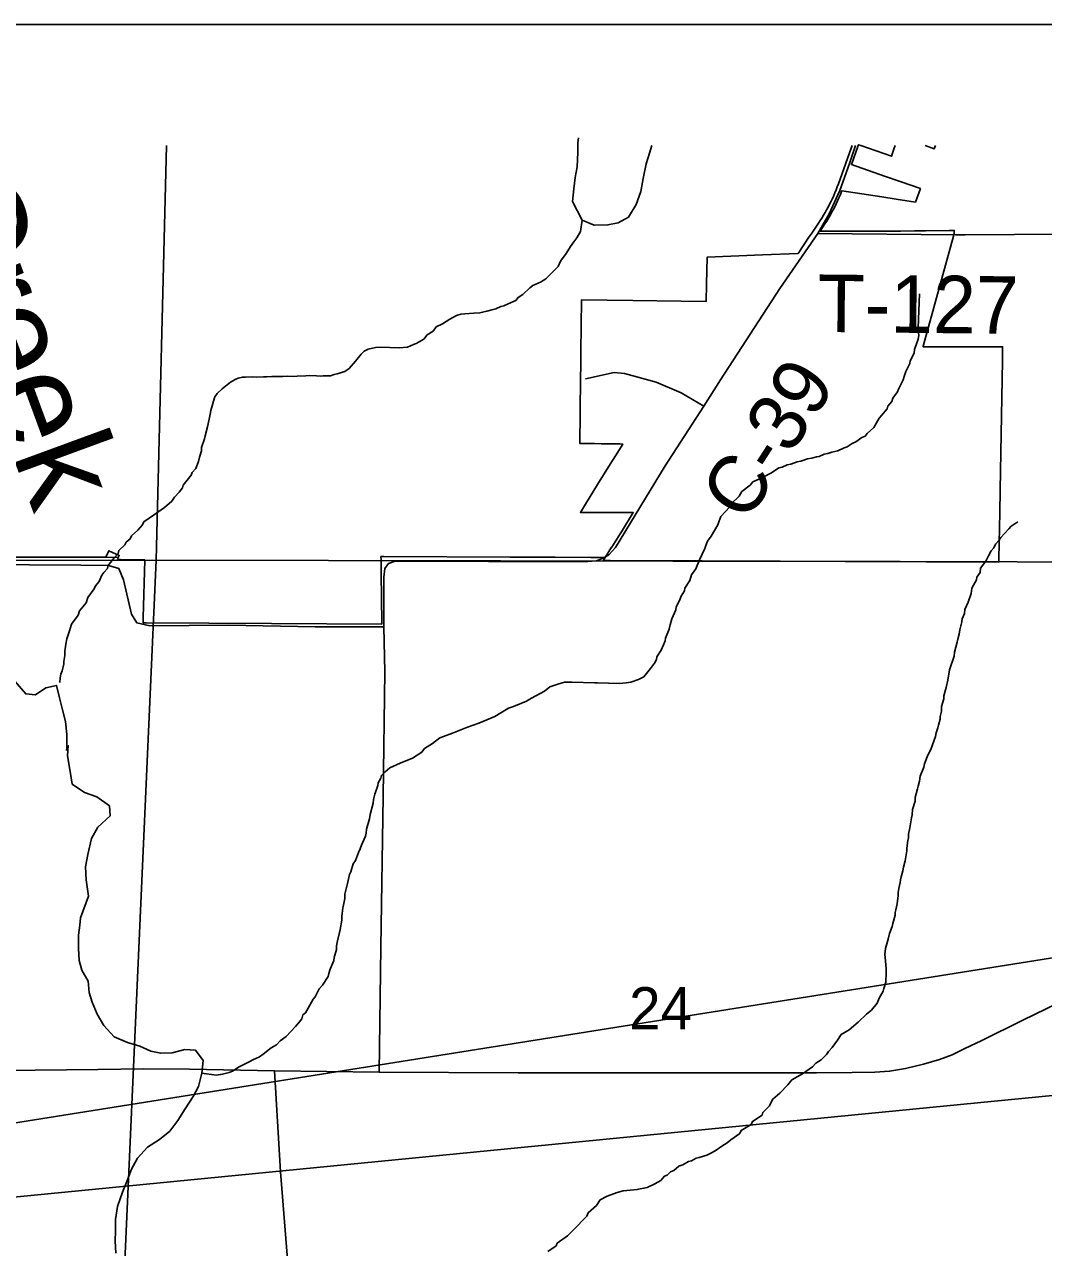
# Model space of a CAD drawing. Extents: x 0 to 34, y 0 to 22.
# Drawn here: x 4.944 to 5.951, y 16.112 to 17.321 of the extents above; entities that cross this region are included whole.
import ezdxf

# ---------------------------------------------------------------- set-up
doc = ezdxf.new("R2010")
doc.units = 0
for name, color, linetype in [('GM_X_County_Road', 7, 'Continuous'), ('GM_X_County_Road_Text', 7, 'Continuous'), ('GM_X_Interchange_Ramps', 7, 'Continuous'), ('GM_X_Minor_Lake', 7, 'Continuous'), ('GM_X_Minor_River', 7, 'Continuous'), ('GM_X_Minor_River_Text', 7, 'Continuous'), ('GM_X_Section', 7, 'Continuous'), ('GM_X_Section_Text', 7, 'Continuous'), ('GM_X_Township_Road', 7, 'Continuous'), ('GM_X_Township_Road_Text', 7, 'Continuous'), ('SH_Data', 7, 'Continuous'), ('SH_Text', 7, 'Continuous')]:
    doc.layers.add(name, color=color, linetype=linetype)

msp = doc.modelspace()

# ---------------------------------------------------------------- linework, layer by layer
at = {"layer": 'GM_X_County_Road'}
msp.add_line((5.1909, 16.287), (5.2943, 16.2857), dxfattribs=at)
for points in [[(5.5248, 16.8009), (5.5278, 16.8041), (5.577, 16.8848), (5.615, 16.944), (5.6316, 16.9698), (5.6902, 17.0601), (5.7276, 17.1146), (5.7389, 17.1338), (5.7495, 17.1571), (5.759, 17.1837), (5.7648, 17.2013)], [(5.2943, 16.2857), (5.2959, 16.4093), (5.2984, 16.5581), (5.2998, 16.6814), (5.2989, 16.7257), (5.2988, 16.7749), (5.2998, 16.7833), (5.3036, 16.7884), (5.3102, 16.7908), (5.3165, 16.7908), (5.4022, 16.7902), (5.5005, 16.7904), (5.5091, 16.7911), (5.5156, 16.7937), (5.5211, 16.7969), (5.5248, 16.8009)], [(5.0905, 15.3548), (5.088, 15.4096), (5.0858, 15.4458), (5.0858, 15.4573), (5.0873, 15.4677), (5.0936, 15.4924), (5.1042, 15.5268), (5.1258, 15.5877), (5.154, 15.6678), (5.187, 15.7631), (5.1955, 15.7965), (5.2044, 15.8401), (5.2156, 15.895), (5.2181, 15.9129), (5.2189, 15.9255), (5.2185, 15.9366), (5.2096, 16.0226), (5.2035, 16.1047), (5.197, 16.1872), (5.1909, 16.287)]]:
    msp.add_lwpolyline(points, dxfattribs=at)
at = {"layer": 'GM_X_Interchange_Ramps'}
for points in [[(5.8042, 17.2013), (5.8032, 17.1987), (5.8005, 17.1909), (5.7701, 17.2014), (5.768, 17.2022), (5.7673, 17.2004), (5.7609, 17.1826), (5.7937, 17.1712), (5.809, 17.1659), (5.8291, 17.1588), (5.8241, 17.1456), (5.805, 17.1485), (5.7911, 17.1506), (5.7515, 17.1567), (5.7498, 17.1525), (5.7486, 17.1496), (5.7472, 17.1467), (5.7459, 17.1438), (5.7444, 17.1407), (5.7429, 17.1379), (5.7414, 17.1351), (5.7398, 17.1323), (5.7382, 17.1296), (5.7365, 17.1268), (5.7348, 17.1241), (5.7331, 17.1215), (5.73, 17.1169), (5.8095, 17.1169), (5.8233, 17.1171), (5.8341, 17.1172), (5.8576, 17.1175), (5.8625, 17.1175), (5.8625, 17.1147), (5.8617, 17.1118), (5.8318, 17.0031), (5.8317, 17.0026), (5.9103, 17.0025), (5.9101, 16.9888), (5.9094, 16.9525), (5.9084, 16.898), (5.9078, 16.8608), (5.9074, 16.8388), (5.9069, 16.8084), (5.9067, 16.7931), (5.9066, 16.7898), (5.8923, 16.7899), (5.878, 16.7899), (5.835, 16.7901), (5.809, 16.7902), (5.7931, 16.7902), (5.7859, 16.7902), (5.6905, 16.7906), (5.6277, 16.7908), (5.6134, 16.7909), (5.6054, 16.7909), (5.5827, 16.791), (5.5224, 16.7912), (5.5175, 16.7912), (5.5157, 16.7912), (5.5159, 16.7916), (5.5176, 16.7944), (5.5162, 16.7944), (5.5067, 16.7944), (5.5033, 16.7944), (5.4681, 16.7945), (5.4237, 16.7947), (5.299, 16.7951), (5.2961, 16.7951), (5.2962, 16.7918), (5.2963, 16.7783), (5.2968, 16.7301), (5.2968, 16.7285), (5.1879, 16.7291), (5.0642, 16.7297), (5.0611, 16.7297), (5.0612, 16.7349), (5.0628, 16.7915), (5.0628, 16.7918), (5.0426, 16.7921), (5.0388, 16.7922), (5.0357, 16.7922), (5.0361, 16.793), (5.0366, 16.7942), (5.0243, 16.7946), (5.0223, 16.7947), (5.0209, 16.7947), (5.02, 16.7947), (5.0172, 16.7947), (5.002, 16.7947), (4.9656, 16.7946), (4.9245, 16.7945)], [(4.9245, 16.7945), (4.9656, 16.7946), (5.002, 16.7947), (5.0172, 16.7947), (5.02, 16.7947), (5.0209, 16.7947), (5.0223, 16.7947), (5.0243, 16.7946), (5.0271, 16.801), (5.0375, 16.7964), (5.0366, 16.7942), (5.0361, 16.793), (5.0357, 16.7922), (5.0388, 16.7922), (5.0426, 16.7921), (5.0628, 16.7918), (5.0628, 16.7915), (5.0612, 16.7349), (5.0611, 16.7297), (5.0642, 16.7297), (5.1879, 16.7291), (5.2968, 16.7285), (5.2968, 16.7301), (5.2963, 16.7783), (5.2962, 16.7918), (5.2961, 16.7951), (5.299, 16.7951), (5.4237, 16.7947), (5.4681, 16.7945), (5.5033, 16.7944), (5.5067, 16.7944), (5.5176, 16.7944), (5.5239, 16.8044), (5.5241, 16.8046), (5.5323, 16.8175), (5.5337, 16.8198), (5.5453, 16.8386), (5.5118, 16.8387), (5.4931, 16.8388), (5.4982, 16.8469), (5.5102, 16.8664), (5.5226, 16.8864), (5.5277, 16.8946), (5.535, 16.9064), (5.532, 16.9065), (5.5137, 16.9067), (5.5071, 16.9068), (5.4925, 16.907), (5.4929, 16.9369), (5.4934, 16.9733), (5.4935, 16.9827), (5.4937, 16.9975), (5.4944, 17.049), (5.5196, 17.0487), (5.5449, 17.0484), (5.5926, 17.0477), (5.6175, 17.0474), (5.6179, 17.0644), (5.6185, 17.0911), (5.6731, 17.0933), (5.7082, 17.0948), (5.719, 17.1107), (5.7211, 17.1139), (5.7224, 17.1158), (5.7283, 17.1247), (5.73, 17.1272), (5.7317, 17.1298), (5.7333, 17.1325), (5.7349, 17.1351), (5.7364, 17.1378), (5.7379, 17.1406), (5.7394, 17.1435), (5.7408, 17.1463), (5.7421, 17.1491), (5.7434, 17.1519), (5.7446, 17.1547), (5.7458, 17.1576), (5.7469, 17.1605), (5.7481, 17.1636), (5.759, 17.1941), (5.7616, 17.2013)], [(5.8439, 17.2013), (5.8428, 17.1982), (5.8339, 17.2013)]]:
    msp.add_lwpolyline(points, dxfattribs=at)
at = {"layer": 'GM_X_Minor_Lake'}
for points in [[(5.4912, 17.209), (5.4907, 17.2041), (5.4905, 17.1946), (5.4898, 17.1805), (5.4881, 17.1699), (5.4867, 17.1586), (5.4853, 17.146), (5.4949, 17.1276)], [(5.4949, 17.1276), (5.5069, 17.1228), (5.5203, 17.1229), (5.5306, 17.125), (5.5406, 17.1305), (5.5481, 17.1433), (5.5529, 17.1561), (5.5551, 17.169), (5.558, 17.1834), (5.5613, 17.194), (5.5636, 17.2013)]]:
    msp.add_lwpolyline(points, dxfattribs=at)
at = {"layer": 'GM_X_Minor_River'}
for points in [[(5.3789, 17.0351), (5.3877, 17.0356), (5.3938, 17.0362), (5.3965, 17.0366), (5.4007, 17.0376), (5.4068, 17.0394), (5.4095, 17.0401), (5.4145, 17.0422), (5.4176, 17.0429), (5.4219, 17.0451), (5.4292, 17.0483), (5.4315, 17.0513), (5.4362, 17.0543), (5.4432, 17.0609), (5.4463, 17.0632), (5.4537, 17.0664), (5.4591, 17.0697), (5.4657, 17.0764), (5.4712, 17.082), (5.4736, 17.0873), (5.4792, 17.0947), (5.4835, 17.1015), (5.4867, 17.1064), (5.4895, 17.1101), (5.4931, 17.1165), (5.4949, 17.1276)], [(5.5818, 16.7278), (5.5834, 16.7335), (5.5875, 16.7425), (5.5879, 16.7455), (5.5912, 16.7519), (5.5928, 16.7561), (5.596, 16.7613), (5.5964, 16.764), (5.6012, 16.7715), (5.6029, 16.7772), (5.6072, 16.7832), (5.6109, 16.7918), (5.6161, 16.8031), (5.617, 16.8062), (5.6186, 16.8103), (5.6225, 16.8155), (5.6289, 16.8264), (5.6298, 16.8295), (5.6318, 16.8347), (5.6408, 16.8444), (5.642, 16.8474), (5.6499, 16.8549), (5.6526, 16.8594), (5.6608, 16.8657), (5.6636, 16.869), (5.6717, 16.8726), (5.6821, 16.8781), (5.6891, 16.8829), (5.6925, 16.8836), (5.6975, 16.8857), (5.701, 16.8864), (5.7072, 16.8889), (5.711, 16.8896), (5.7175, 16.8917), (5.7217, 16.8924), (5.7263, 16.8938), (5.729, 16.8941), (5.734, 16.8963), (5.7375, 16.8969), (5.7417, 16.8984), (5.7475, 16.8997), (5.7536, 16.9026), (5.7567, 16.9037), (5.7618, 16.907), (5.7652, 16.9085), (5.7711, 16.9129), (5.7745, 16.9143), (5.7765, 16.9169), (5.7831, 16.9229), (5.7883, 16.9319), (5.7907, 16.9345), (5.7962, 16.9412), (5.797, 16.9439), (5.8009, 16.9483), (5.8018, 16.9517), (5.8065, 16.9581), (5.8074, 16.9608), (5.8122, 16.9698), (5.813, 16.9732), (5.8147, 16.9781), (5.8187, 16.986), (5.8191, 16.9886), (5.8228, 16.9962), (5.8232, 17), (5.8269, 17.0102), (5.8274, 17.0136), (5.8271, 17.0163), (5.8268, 17.0212), (5.8281, 17.0547)], [(4.9788, 16.6707), (4.9793, 16.6753), (4.9797, 16.6791), (4.981, 16.6821), (4.9827, 16.6889), (4.9827, 16.6916), (4.9836, 16.6973), (4.9838, 16.7018), (4.9847, 16.7087), (4.9856, 16.714), (4.9885, 16.7219), (4.9905, 16.7283), (4.9969, 16.7373), (4.9981, 16.7415), (5.0048, 16.7493), (5.0065, 16.7546), (5.0128, 16.7632), (5.014, 16.7662), (5.0176, 16.7707), (5.0204, 16.7768), (5.0224, 16.7794), (5.0259, 16.7835), (5.0267, 16.7865), (5.0326, 16.794), (5.0366, 16.7981), (5.037, 16.8011), (5.0429, 16.8067), (5.0445, 16.8093), (5.0484, 16.8127), (5.0496, 16.8157), (5.0558, 16.8212), (5.0605, 16.8265), (5.0618, 16.8295), (5.0722, 16.8368), (5.0823, 16.8438), (5.0894, 16.8501), (5.0921, 16.8539), (5.0968, 16.8587), (5.1, 16.8632), (5.1008, 16.8659), (5.1087, 16.8756), (5.1095, 16.8782), (5.1131, 16.8823), (5.1159, 16.8891), (5.1168, 16.8933), (5.1189, 16.8997), (5.1189, 16.9031), (5.1218, 16.9114), (5.1223, 16.9145), (5.1248, 16.9235), (5.1265, 16.9311), (5.1274, 16.936), (5.1279, 16.9395), (5.1308, 16.9489), (5.1321, 16.9531), (5.1344, 16.9564), (5.1391, 16.9609), (5.1473, 16.9676), (5.1519, 16.9701), (5.155, 16.9716), (5.1592, 16.9726), (5.1623, 16.9725), (5.1688, 16.9728), (5.1733, 16.9726), (5.1802, 16.9729), (5.1833, 16.9728), (5.1882, 16.973), (5.192, 16.973), (5.1993, 16.9732), (5.2035, 16.9734), (5.2096, 16.9733), (5.2134, 16.9736), (5.2218, 16.9738), (5.2252, 16.9741), (5.2325, 16.9739), (5.2363, 16.9734), (5.2389, 16.9737), (5.2462, 16.9739), (5.25, 16.975), (5.2527, 16.9757), (5.2604, 16.9782), (5.2647, 16.9811), (5.271, 16.9882), (5.2765, 16.9953), (5.2796, 16.9983), (5.2835, 17.0001), (5.2907, 17.0018), (5.2953, 17.0021), (5.314, 17.0016), (5.3224, 17.0022), (5.3282, 17.0047), (5.3309, 17.0058), (5.3386, 17.0102), (5.3418, 17.0143), (5.3476, 17.0179), (5.3507, 17.0221), (5.3569, 17.0253), (5.3643, 17.0297), (5.3709, 17.0334), (5.3751, 17.0348), (5.3789, 17.0351)], [(5.8287, 16.5782), (5.8324, 16.5869), (5.8332, 16.5903), (5.8357, 16.5971), (5.8369, 16.5997), (5.8393, 16.6046), (5.8439, 16.6175), (5.8447, 16.6209), (5.8464, 16.6258), (5.8468, 16.6284), (5.8485, 16.6345), (5.8486, 16.6371), (5.8498, 16.6424), (5.85, 16.647), (5.8521, 16.6546), (5.8521, 16.6576), (5.8546, 16.6659), (5.8563, 16.6731), (5.8578, 16.6834), (5.8623, 16.6966), (5.8628, 16.7008), (5.8653, 16.7106), (5.8662, 16.7137), (5.8674, 16.7186), (5.8679, 16.7228), (5.87, 16.7307), (5.8705, 16.7338), (5.8725, 16.739), (5.873, 16.7428), (5.8762, 16.75), (5.8791, 16.7587), (5.88, 16.764), (5.8844, 16.7723), (5.8849, 16.7749), (5.8881, 16.7794), (5.8886, 16.7836), (5.8937, 16.7907), (5.8965, 16.796), (5.8989, 16.8009), (5.9017, 16.8038), (5.9033, 16.8076), (5.9068, 16.8113), (5.9084, 16.814), (5.9123, 16.8181), (5.9166, 16.8225), (5.9186, 16.8251), (5.9225, 16.8277), (5.9252, 16.8296)], [(4.9854, 16.6035), (4.9856, 16.6063), (4.9856, 16.6192), (4.9844, 16.6322), (4.9813, 16.6437), (4.9786, 16.6556), (4.9755, 16.6678), (4.9651, 16.6655), (4.9547, 16.6585), (4.9452, 16.6595), (4.9345, 16.672), (4.9298, 16.6817), (4.9271, 16.6947), (4.9217, 16.707), (4.9178, 16.7166), (4.9212, 16.7283), (4.9242, 16.7396), (4.9253, 16.7533), (4.9206, 16.7633), (4.9144, 16.7741), (4.9075, 16.7861), (4.9001, 16.7939)], [(5.1192, 16.2846), (5.1334, 16.2825), (5.1395, 16.2835), (5.1461, 16.2853), (5.1495, 16.2867), (5.1561, 16.2908), (5.1665, 16.2962), (5.1696, 16.2977), (5.1762, 16.3009), (5.1797, 16.3035), (5.1875, 16.3098), (5.1929, 16.3127), (5.1964, 16.3165), (5.2026, 16.3209), (5.2116, 16.3306), (5.2156, 16.3354), (5.2179, 16.3384), (5.2188, 16.3422), (5.2215, 16.3441), (5.2243, 16.3489), (5.2291, 16.3576), (5.2311, 16.3602), (5.2351, 16.3681), (5.2382, 16.3715), (5.2438, 16.3801), (5.2446, 16.3831), (5.2459, 16.3873), (5.2496, 16.396), (5.25, 16.399), (5.2521, 16.407), (5.2522, 16.4104), (5.2531, 16.4153), (5.2552, 16.4236), (5.2557, 16.4267), (5.2574, 16.4358), (5.2575, 16.4396), (5.2585, 16.448), (5.259, 16.4506), (5.2603, 16.4574), (5.2604, 16.4616), (5.2612, 16.4643), (5.263, 16.4722), (5.2638, 16.4749), (5.2651, 16.4809), (5.2663, 16.4836), (5.2688, 16.4915), (5.2708, 16.4949), (5.274, 16.5028), (5.2757, 16.5062), (5.2769, 16.51), (5.2809, 16.519), (5.2814, 16.5217), (5.2819, 16.5259), (5.2848, 16.5361), (5.2853, 16.5403), (5.2883, 16.5516), (5.2887, 16.555), (5.29, 16.5604), (5.2929, 16.569), (5.2934, 16.5717), (5.2961, 16.5762), (5.2966, 16.5789), (5.3001, 16.5826), (5.3048, 16.5863), (5.3152, 16.591), (5.3272, 16.596), (5.3365, 16.6019), (5.3392, 16.6056), (5.347, 16.6104), (5.3544, 16.6159), (5.3578, 16.6174), (5.3667, 16.6206), (5.3817, 16.6267), (5.3929, 16.6306), (5.4086, 16.6371), (5.4222, 16.6452), (5.4272, 16.6469), (5.4399, 16.6524), (5.445, 16.6553), (5.4577, 16.6622), (5.4628, 16.6663), (5.4708, 16.6691), (5.4774, 16.6709), (5.485, 16.6711), (5.5071, 16.6705), (5.5101, 16.6705), (5.5319, 16.6699), (5.5384, 16.6705), (5.5429, 16.6712), (5.5506, 16.6737), (5.5557, 16.6762), (5.5624, 16.6844), (5.5663, 16.6897), (5.5683, 16.6934), (5.5688, 16.6961), (5.5731, 16.7028), (5.5752, 16.7081), (5.5768, 16.7119), (5.5772, 16.7146), (5.5809, 16.7236), (5.5818, 16.7278)], [(4.9856, 16.6063), (4.9871, 16.6084), (4.9865, 16.5981), (4.9889, 16.5829), (4.9909, 16.5703), (5.0033, 16.5621), (5.0154, 16.5576), (5.0278, 16.5487), (5.0287, 16.5388), (5.0163, 16.5276), (5.01, 16.5167), (5.0066, 16.5008), (5.0041, 16.4887), (5.005, 16.4757), (5.0073, 16.4597), (4.9991, 16.4382)], [(5.4863, 16.1299), (5.4906, 16.134), (5.4953, 16.1389), (5.4996, 16.1433), (5.5008, 16.1467), (5.509, 16.1538), (5.5126, 16.1594), (5.5195, 16.1631), (5.5295, 16.1666), (5.5353, 16.1684), (5.546, 16.1693), (5.549, 16.1696), (5.5521, 16.1703), (5.5559, 16.1709), (5.559, 16.1716), (5.5667, 16.1753), (5.5725, 16.1786), (5.5761, 16.1827), (5.5788, 16.1837), (5.5823, 16.1871), (5.5854, 16.1885), (5.5904, 16.1926), (5.5943, 16.194), (5.6001, 16.1973), (5.6028, 16.198), (5.6074, 16.2006), (5.6105, 16.2013), (5.6182, 16.2037), (5.6232, 16.2063), (5.6274, 16.2085), (5.6329, 16.2125), (5.6383, 16.2158), (5.6418, 16.2188), (5.6507, 16.2251), (5.652, 16.2281), (5.662, 16.2339), (5.6632, 16.237), (5.6726, 16.2432), (5.6734, 16.2459), (5.68, 16.2522), (5.6809, 16.2548), (5.6833, 16.259), (5.6903, 16.2649), (5.6981, 16.2731), (5.702, 16.2779), (5.7125, 16.2838), (5.7226, 16.2908), (5.7257, 16.2945), (5.7311, 16.2978), (5.7362, 16.303), (5.7382, 16.306), (5.7418, 16.3101), (5.7473, 16.3172), (5.7509, 16.3229), (5.7586, 16.3276), (5.7676, 16.3351), (5.7758, 16.3429), (5.7808, 16.3469), (5.7863, 16.3537), (5.7884, 16.3589), (5.7924, 16.3657), (5.7928, 16.3684), (5.7949, 16.3744), (5.7949, 16.3771), (5.7954, 16.3812), (5.7952, 16.3881), (5.7947, 16.3954), (5.7941, 16.4022), (5.7946, 16.4079), (5.7971, 16.417), (5.7984, 16.4227), (5.8013, 16.4295), (5.8017, 16.4325), (5.8042, 16.4409), (5.8043, 16.4435), (5.8047, 16.4462), (5.806, 16.4519), (5.807, 16.4602), (5.8071, 16.4633), (5.8079, 16.4671), (5.8092, 16.4731), (5.8093, 16.4758), (5.8102, 16.4788), (5.8118, 16.4845), (5.8123, 16.4883), (5.814, 16.4944), (5.8158, 16.5042), (5.8158, 16.5069), (5.8168, 16.5145), (5.8172, 16.5171), (5.8173, 16.5209), (5.8186, 16.527), (5.8204, 16.5369), (5.8209, 16.5399), (5.8214, 16.5452), (5.8239, 16.5535), (5.824, 16.557), (5.8261, 16.5657), (5.827, 16.5683), (5.8282, 16.5733), (5.8287, 16.5782)], [(5.0496, 16.1899), (5.0556, 16.2007), (5.0654, 16.2115), (5.0774, 16.2191), (5.0875, 16.2272), (5.0954, 16.2377), (5.1026, 16.2493), (5.1106, 16.2616), (5.1158, 16.2713), (5.1192, 16.2846), (5.1203, 16.2971), (5.1129, 16.3072), (5.1023, 16.3079), (5.0897, 16.3048), (5.0786, 16.3043), (5.0688, 16.3065), (5.0579, 16.3114), (5.0458, 16.3148), (5.0326, 16.3205), (5.0223, 16.3318), (5.0157, 16.343), (5.0107, 16.3549), (5.0079, 16.3645), (5.0067, 16.3756), (5.0005, 16.3864), (4.9978, 16.396), (4.9973, 16.4082), (4.9973, 16.4211), (4.9987, 16.431), (4.9991, 16.4382)], [(5.034, 16.1066), (5.0336, 16.1188), (5.0339, 16.1287), (5.0338, 16.1401), (5.0357, 16.153), (5.0406, 16.1669), (5.0451, 16.1774), (5.0496, 16.1899)], [(5.4609, 16.1084), (5.4691, 16.114), (5.4703, 16.1166), (5.4804, 16.124), (5.4863, 16.1299)]]:
    msp.add_lwpolyline(points, dxfattribs=at)
at = {"layer": 'GM_X_Section'}
for points in [[(5.0842, 17.2013), (5.0741, 16.7917), (4.0439, 16.7912), (4.0506, 17.2013)], [(6.0995, 17.2013), (6.0948, 16.7898), (5.0741, 16.7917), (5.0842, 17.2013)]]:
    msp.add_lwpolyline(points, dxfattribs=at)
for points in [[(4.0439, 16.7912), (5.0741, 16.7917), (5.0286, 15.7742), (4.0274, 15.7833)], [(5.0741, 16.7917), (6.0948, 16.7898), (6.0861, 15.9241), (5.7249, 15.8958), (5.3975, 15.7702), (5.0286, 15.7742)]]:
    msp.add_lwpolyline(points, close=True, dxfattribs=at)
at = {"layer": 'GM_X_Township_Road'}
for p, q in [((5.7276, 17.1146), (5.8637, 17.1133)), ((5.1909, 16.287), (5.2943, 16.2857))]:
    msp.add_line(p, q, dxfattribs=at)
for points in [[(5.8637, 17.1133), (5.8734, 17.1132), (6.0677, 17.1144)], [(5.615, 16.944), (5.5928, 16.957), (5.5681, 16.9675), (5.5368, 16.976), (5.5265, 16.977), (5.4983, 16.971)], [(4.6796, 16.7902), (4.8466, 16.7876), (4.9997, 16.7868), (5.027, 16.7864), (5.0372, 16.7835), (5.0418, 16.7723), (5.0496, 16.7383), (5.0548, 16.7297), (5.0678, 16.7267), (5.1454, 16.7273), (5.231, 16.7259), (5.2989, 16.7257)], [(5.2943, 16.2857), (5.4318, 16.285), (5.5785, 16.285), (5.7265, 16.285), (5.7616, 16.2852), (5.7842, 16.2855), (5.7987, 16.2865), (5.8142, 16.2893), (5.8323, 16.2935), (5.8479, 16.2982), (5.8604, 16.3029), (5.8731, 16.3089), (5.889, 16.3167), (5.9303, 16.337), (5.9763, 16.3595)], [(4.9236, 16.2874), (5.0163, 16.2882), (5.0616, 16.2888), (5.1068, 16.2886), (5.1909, 16.287)]]:
    msp.add_lwpolyline(points, dxfattribs=at)
at = {"layer": 'SH_Data'}
msp.add_line((2, 17.3211), (9, 17.3211), dxfattribs=at)
at = {"layer": 'SH_Text'}
msp.add_lwpolyline([(9.6169, 16.9806), (3.7384, 16.0451), (9.6169, 16.6206)], close=True, dxfattribs=at)

# ---------------------------------------------------------------- texts
at = {"layer": 'GM_X_County_Road_Text'}
msp.add_text('C-39', height=0.05682, rotation=57.1434, dxfattribs=at).set_placement((5.6571, 16.8273))
at = {"layer": 'GM_X_Minor_River_Text'}
msp.add_text('Creek', height=0.0947, rotation=290.1517, dxfattribs=at).set_placement((4.8369, 17.1541))
at = {"layer": 'GM_X_Section_Text'}
msp.add_text('24', height=0.04186, rotation=0, dxfattribs=at).set_placement((5.5413, 16.3278))
at = {"layer": 'GM_X_Township_Road_Text'}
msp.add_text('T-127', height=0.05682, rotation=359.4386, dxfattribs=at).set_placement((5.7274, 17.0172))

doc.saveas('drawing.dxf')
